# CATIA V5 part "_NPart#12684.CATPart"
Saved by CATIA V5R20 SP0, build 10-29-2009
Part number: DIN6325 Ø3X32
Revision: ANY
Definition: UNKNOWN
Nomenclature: DIN6325 Ø3X32
Source: Unknown
Bounding box of the stored display mesh (mm): x -1.5 to 1.5, y 0 to 32, z -1.5 to 1.5
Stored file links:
  C:\Users\Utente\Desktop\IO LAVORO\3D X SITO CF\CUMSA\3D files AE\AE 052430\_NPart#12684.CATPart
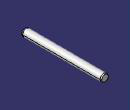
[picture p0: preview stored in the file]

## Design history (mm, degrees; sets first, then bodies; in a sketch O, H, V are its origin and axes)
Body1 "Revolución1" (main body)
  Solid1: solid without history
